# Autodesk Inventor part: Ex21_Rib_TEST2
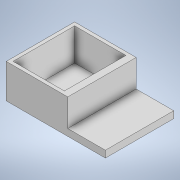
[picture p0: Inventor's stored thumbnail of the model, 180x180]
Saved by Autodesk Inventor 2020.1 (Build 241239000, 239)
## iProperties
Created: 2019-11
Part Number: Ex21_Rib_TEST2
Material: Generic
Document SubType Name: Modeling
Designer: Synergysoft Dell02
Density: 1 g/cm^3
Appearance: Default
Author: Synergysoft Dell02
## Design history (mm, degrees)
sketch "Sketch1"
  geometry: L1 (0, 0)-(0, 50); L2 (0, 50)-(10, 50); L3 (10, 50)-(10, 10); L4 (10, 10)-(65, 10); L5 (65, 10)-(65, 0); L6 (65, 0)-(0, 0); L7 (0, 50)-(-80, 50); L8 (-80, 50)-(-80, 0); L9 (-80, 0)-(0, 0); L10 (0, 0)-(0, 50); 1 further point
  constraints: 20 end point, 5 perpendicular, 3 parallel, 2 horizontal, 1 vertical
  dimensions: "d1" = 10 distance of L1.end L2.end; "d3" = 10 distance of L4.end L5.end; "d4" = 65 distance of L5.end L1.start; "d5" = 80 distance of L9.end L8.end; "d6" = 50 distance of L8.end L7.end
extrude "Extrusion1" new body sketch "Sketch1" distance "d7" = 100; taper "d8" = 0 deg
sketch "Sketch3"
  geometry: L1 (0, 0)-(0, -100) reference; L2 (90, 0)-(0, 0) reference; L3 (90, -100)-(0, -100) reference; L4 (90, 0)-(90, -100) reference; L5 (80, -5)-(5, -5); L6 (5, -5)-(5, -95); L7 (5, -95)-(80, -95); L8 (80, -5)-(80, -95); 1 further point
  constraints: 8 end point, 1 parallel
  dimensions: "d12" = 5 distance between parallel lines of L2 L5; "d13" = 10 distance between parallel lines of L4 L8; "d14" = 5 distance between parallel lines of L6 L1 (= d12); "d15" = 5 distance between parallel lines of L3 L7 (= d12)
extrude "Extrusion3" cut sketch "Sketch3" stored distance "d16" = 10; taper "d17" = -10 deg
body "Solid1"
